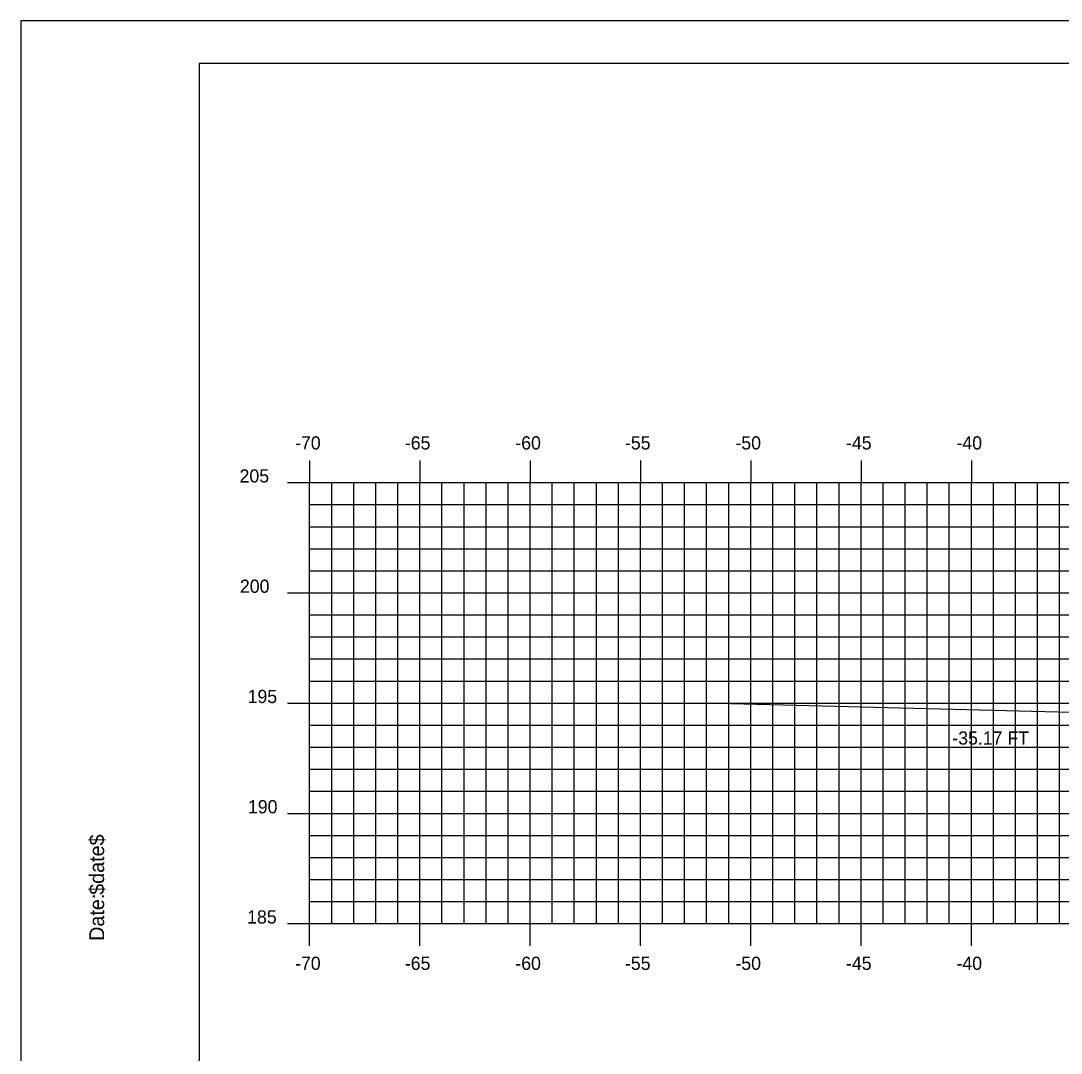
# Model space of a CAD drawing. Extents: x 1138985 to 1139155, y 608981 to 609091.
# Drawn here: x 1138984.86 to 1139032.02, y 609044.46 to 609091.28 of the extents above; entities that cross this region are included whole.
import ezdxf

# ---------------------------------------------------------------- set-up
doc = ezdxf.new("R2010")
doc.units = 0
for name, color, linetype in [('BORDER', 7, 'Continuous'), ('D_Text_Standard', 7, 'Continuous'), ('H_V ANNOTATION', 7, 'Continuous'), ('MAJOR', 7, 'Continuous'), ('MINOR', 7, 'Continuous'), ('PLOT BOUNDARY', 7, 'Continuous'), ('S_Roadway_Centerline', 7, 'Continuous')]:
    doc.layers.add(name, color=color, linetype=linetype)

msp = doc.modelspace()

# ---------------------------------------------------------------- linework, layer by layer
at = {"layer": 'BORDER'}
msp.add_lwpolyline([(1138992.949, 608984.335), (1139152.949, 608984.335), (1139152.949, 609089.335), (1138992.949, 609089.335)], close=True, dxfattribs=at)
at = {"layer": 'MAJOR'}
for p, q in [((1138997.949, 609071.337), (1138997.949, 609070.335)), ((1139002.949, 609071.337), (1139002.949, 609070.335)), ((1139007.949, 609071.337), (1139007.949, 609070.335)), ((1139012.949, 609071.337), (1139012.949, 609070.335)), ((1139017.949, 609071.337), (1139017.949, 609070.335)), ((1139022.949, 609071.337), (1139022.949, 609070.335)), ((1139027.949, 609071.337), (1139027.949, 609070.335)), ((1138996.947, 609070.335), (1138997.949, 609070.335)), ((1138997.949, 609070.335), (1139137.949, 609070.335)), ((1138997.949, 609050.335), (1138997.949, 609070.335)), ((1138997.949, 609050.335), (1138997.949, 609070.335)), ((1138997.949, 609070.335), (1139137.949, 609070.335)), ((1139002.949, 609050.335), (1139002.949, 609070.335)), ((1139007.949, 609050.335), (1139007.949, 609070.335)), ((1139012.949, 609050.335), (1139012.949, 609070.335)), ((1139017.949, 609050.335), (1139017.949, 609070.335)), ((1139022.949, 609050.335), (1139022.949, 609070.335)), ((1139027.949, 609050.335), (1139027.949, 609070.335)), ((1138996.947, 609065.335), (1138997.949, 609065.335)), ((1138997.949, 609065.335), (1139137.949, 609065.335)), ((1138996.947, 609060.335), (1138997.949, 609060.335)), ((1138997.949, 609060.335), (1139137.949, 609060.335)), ((1138996.947, 609055.335), (1138997.949, 609055.335)), ((1138997.949, 609055.335), (1139137.949, 609055.335)), ((1138996.947, 609050.335), (1138997.949, 609050.335)), ((1138997.949, 609050.335), (1139137.949, 609050.335)), ((1138997.949, 609050.335), (1139137.949, 609050.335)), ((1138997.949, 609049.333), (1138997.949, 609050.335)), ((1139002.949, 609049.333), (1139002.949, 609050.335)), ((1139007.949, 609049.333), (1139007.949, 609050.335)), ((1139012.949, 609049.333), (1139012.949, 609050.335)), ((1139017.949, 609049.333), (1139017.949, 609050.335)), ((1139022.949, 609049.333), (1139022.949, 609050.335)), ((1139027.949, 609049.333), (1139027.949, 609050.335))]:
    msp.add_line(p, q, dxfattribs=at)
at = {"layer": 'MINOR'}
for p, q in [((1138998.949, 609050.335), (1138998.949, 609070.335)), ((1138999.949, 609050.335), (1138999.949, 609070.335)), ((1139000.949, 609050.335), (1139000.949, 609070.335)), ((1139001.949, 609050.335), (1139001.949, 609070.335)), ((1139003.949, 609050.335), (1139003.949, 609070.335)), ((1139004.949, 609050.335), (1139004.949, 609070.335)), ((1139005.949, 609050.335), (1139005.949, 609070.335)), ((1139006.949, 609050.335), (1139006.949, 609070.335)), ((1139008.949, 609050.335), (1139008.949, 609070.335)), ((1139009.949, 609050.335), (1139009.949, 609070.335)), ((1139010.949, 609050.335), (1139010.949, 609070.335)), ((1139011.949, 609050.335), (1139011.949, 609070.335)), ((1139013.949, 609050.335), (1139013.949, 609070.335)), ((1139014.949, 609050.335), (1139014.949, 609070.335)), ((1139015.949, 609050.335), (1139015.949, 609070.335)), ((1139016.949, 609050.335), (1139016.949, 609070.335)), ((1139018.949, 609050.335), (1139018.949, 609070.335)), ((1139019.949, 609050.335), (1139019.949, 609070.335)), ((1139020.949, 609050.335), (1139020.949, 609070.335)), ((1139021.949, 609050.335), (1139021.949, 609070.335)), ((1139023.949, 609050.335), (1139023.949, 609070.335)), ((1139024.949, 609050.335), (1139024.949, 609070.335)), ((1139025.949, 609050.335), (1139025.949, 609070.335)), ((1139026.949, 609050.335), (1139026.949, 609070.335)), ((1139028.949, 609050.335), (1139028.949, 609070.335)), ((1139029.949, 609050.335), (1139029.949, 609070.335)), ((1139030.949, 609050.335), (1139030.949, 609070.335)), ((1139031.949, 609050.335), (1139031.949, 609070.335)), ((1138997.949, 609069.335), (1139137.949, 609069.335)), ((1138997.949, 609069.335), (1138998.951, 609069.335)), ((1138997.949, 609068.335), (1139137.949, 609068.335)), ((1138997.949, 609068.335), (1138998.951, 609068.335)), ((1138997.949, 609067.335), (1139137.949, 609067.335)), ((1138997.949, 609067.335), (1138998.951, 609067.335)), ((1138997.949, 609066.335), (1139137.949, 609066.335)), ((1138997.949, 609066.335), (1138998.951, 609066.335)), ((1138997.949, 609064.335), (1139137.949, 609064.335)), ((1138997.949, 609064.335), (1138998.951, 609064.335)), ((1138997.949, 609063.335), (1139137.949, 609063.335)), ((1138997.949, 609063.335), (1138998.951, 609063.335)), ((1138997.949, 609062.335), (1139137.949, 609062.335)), ((1138997.949, 609062.335), (1138998.951, 609062.335)), ((1138997.949, 609061.335), (1139137.949, 609061.335)), ((1138997.949, 609061.335), (1138998.951, 609061.335)), ((1138997.949, 609059.335), (1139137.949, 609059.335)), ((1138997.949, 609059.335), (1138998.951, 609059.335)), ((1138997.949, 609058.335), (1139137.949, 609058.335)), ((1138997.949, 609058.335), (1138998.951, 609058.335)), ((1138997.949, 609057.335), (1139137.949, 609057.335)), ((1138997.949, 609057.335), (1138998.951, 609057.335)), ((1138997.949, 609056.335), (1139137.949, 609056.335)), ((1138997.949, 609056.335), (1138998.951, 609056.335)), ((1138997.949, 609054.335), (1139137.949, 609054.335)), ((1138997.949, 609054.335), (1138998.951, 609054.335)), ((1138997.949, 609053.335), (1139137.949, 609053.335)), ((1138997.949, 609053.335), (1138998.951, 609053.335)), ((1138997.949, 609052.335), (1139137.949, 609052.335)), ((1138997.949, 609052.335), (1138998.951, 609052.335)), ((1138997.949, 609051.335), (1139137.949, 609051.335)), ((1138997.949, 609051.335), (1138998.951, 609051.335))]:
    msp.add_line(p, q, dxfattribs=at)
at = {"layer": 'PLOT BOUNDARY'}
msp.add_lwpolyline([(1138984.856, 608981.276), (1139154.856, 608981.276), (1139154.856, 609091.276), (1138984.856, 609091.276)], close=True, dxfattribs=at)
at = {"layer": 'S_Roadway_Centerline'}
msp.add_lwpolyline([(1139016.434, 609060.334), (1139031.885, 609059.945), (1139034.377, 609059.859), (1139052.189, 609059.505), (1139054.799, 609059.411), (1139055.727, 609059.439), (1139059.616, 609059.763), (1139066.017, 609059.781), (1139070.197, 609059.83), (1139070.369, 609060.059), (1139076.793, 609059.71), (1139080.407, 609059.613), (1139083.326, 609059.173), (1139084.343, 609059.069), (1139087.733, 609057.962), (1139089.051, 609057.481), (1139090.872, 609057.361), (1139093.183, 609057.505), (1139095.448, 609057.872), (1139096.555, 609058.182), (1139104.125, 609058.757), (1139115.082, 609058.5), (1139137.949, 609058.777)], dxfattribs=at)

# ---------------------------------------------------------------- texts
at = {"layer": 'BORDER'}
for s, p in [('$date$', (1138988.634, 609051.64)), ('Date:', (1138988.634, 609049.552))]:
    msp.add_text(s, height=0.6696, rotation=90, dxfattribs=at).set_placement(p)
at = {"layer": 'D_Text_Standard'}
msp.add_text('-35.17 FT', height=0.6, dxfattribs=at).set_placement((1139027.085, 609058.451))
at = {"layer": 'H_V ANNOTATION'}
for s, p in [('-70', (1138997.29, 609071.835)), ('-65', (1139002.266, 609071.835)), ('-60', (1139007.274, 609071.835)), ('-55', (1139012.245, 609071.835)), ('-50', (1139017.253, 609071.835)), ('-45', (1139022.266, 609071.835)), ('-40', (1139027.274, 609071.835)), ('205', (1138994.773, 609070.335)), ('200', (1138994.789, 609065.335)), ('195', (1138995.138, 609060.335)), ('190', (1138995.154, 609055.335)), ('185', (1138995.116, 609050.335)), ('-70', (1138997.29, 609048.235)), ('-65', (1139002.266, 609048.235)), ('-60', (1139007.274, 609048.235)), ('-55', (1139012.245, 609048.235)), ('-50', (1139017.253, 609048.235)), ('-45', (1139022.266, 609048.235)), ('-40', (1139027.274, 609048.235))]:
    msp.add_text(s, height=0.6, dxfattribs=at).set_placement(p)
at = {"layer": 'MAJOR'}
msp.add_text('-', height=0.006, dxfattribs=at).set_placement((1138997.944, 609050.335))

doc.saveas('drawing.dxf')
